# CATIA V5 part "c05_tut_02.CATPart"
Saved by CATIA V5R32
Part number: Part1
Bounding box of the stored display mesh (mm): x -5 to 20, y -42.072 to 42.072, z 0 to 101.82
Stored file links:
  D:\PROJECTS\Project 2022\CATIA V5 6R 2022\Resources\Tutorial Files\c05_catia_v5_6r2022_tut\c05_tut_02.CATPart
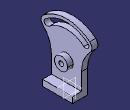
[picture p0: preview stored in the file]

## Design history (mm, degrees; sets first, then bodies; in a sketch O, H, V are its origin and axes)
Body1 (main body)
  Sketch1 on yz-plane, origin (0, 0, 0), H (0, 1, 0), V (0, 0, 1)
    point P1 (-25, 0)
    line L1 (-25, 0) -> (25, 0)
    point P2 (25, 0)
    line L2 (-25, 0) -> (-25, 38.3145)
    point P3 (-25, 38.3145)
    arc A1 centre (0, 42) radius 60 from (38.5673, 87.9627) to (-38.5673, 87.9627) ccw
    point P4 (0, 42)
    axis line L3 (0, 42) -> (-54.0665, 106.434)
    point P5 (-54.0665, 106.434)
    point P6 (54.0665, 106.434)
    point P7 (0, 42)
    construction line L4 (0, 42) -> (54.0665, 106.434)
    point P8 (-38.5673, 87.9627)
    point P9 (38.5673, 87.9627)
    arc A2 centre (-32.1394, 80.3022) radius 10 from (-38.5673, 87.9627) to (-39.2828, 73.3043) ccw
    point P10 (-32.1394, 80.3022)
    arc A3 centre (32.1394, 80.3022) radius 10 from (38.5673, 87.9627) to (39.2828, 73.3043) cw
    arc A4 centre (-75, 38.3145) radius 50 from (-25, 38.3145) to (-39.2828, 73.3043) ccw
    arc A5 centre (75, 38.3145) radius 50 from (25, 38.3145) to (39.2828, 73.3043) cw
    point P14 (25, 38.3145)
    point P15 (25, 0)
    line L5 (25, 0) -> (25, 38.3145)
    point P17 (25, 38.3145)
    length L1 = 50
    angle L4 L3 = 80
    radius A1 = 60
    radius A2 = 10
    radius A5 = 50
    distance P4 L1 = 42
    coincidence: P1 H, P4 V, L3 P8, L4 P9, P10 L3, L5 P17, P2 P15, P14 P17
    horizontal: L1 H
    symmetry: P2 P1 V, P5 P6 V, P4 P7 V, L3 L4 V, A2 A3 V, A4 A5 V, P3 P14 V, P1 P15 V, L2 L5 V
    vertical: L2 V
    tangency: A2 A1, A4 A2, A4 L2, A5 A3, L5 A5
  Pad1: profile Sketch1, direction (1, 0, 0), length 5, mirrored extent
  Sketch2 on start face of Pad1, origin (-5, 0, 0), H (0, -1, 0), V (0, 0, 1)
    construction arc A1 centre (0, 42) radius 50 from (32.1394, 80.3022) to (-32.1394, 80.3022) ccw
    point P1 (0, 42)
    arc A2 centre (32.1394, 80.3022) radius 5 from (35.3533, 84.1324) to (28.9254, 76.472) cw
    arc A3 centre (-32.1394, 80.3022) radius 5 from (-28.9254, 76.472) to (-35.3533, 84.1324) cw
    arc A4 centre (0, 42) radius 45 from (28.9254, 76.472) to (-28.9254, 76.472) ccw
    arc A5 centre (0, 42) radius 55 from (-35.3533, 84.1324) to (35.3533, 84.1324) cw
    construction line L1 (-32.1394, 80.3022) -> (0, 42)
    construction line L2 (0, 42) -> (32.1394, 80.3022)
    radius A3 = 5
    radius A1 = 50
    angle L2 L1 = 80
    angle L2 V = 40
    distance P1 H = 42
    coincidence: P1 V
    tangency: A4 A3, A3 A5, A5 A2, A2 A4
    concentricity: A4 P1, A5 P1
  Pocket1: profile Sketch2, direction (1, 0, 0), through (limit type 6)
  Sketch3 on end face of Pad1, origin (5, 0, 0), H (0, 1, 0), V (0, 0, 1)
    point P1 (-24.9592, 0)
    line L1 (-24.9592, 0) -> (25, 0)
    line L2 (25, 0) -> (25, 10)
    line L3 (25, 10) -> (-24.9592, 10)
    line L4 (-24.9592, 10) -> (-24.9592, 0)
    reference projected line E1 (25, 0) -> (25, 38.3145) from edge [face of Pad1 from Sketch1.L5 | end face of Pad1]
    distance L1 L3 = 10
    distance L2 L4 = 49.9592
    coincidence: P1 H, L2 E1
    horizontal: L1 H, L3 H
    vertical: L2 V, L4 V
  Pad2: profile Sketch3, direction (1, 0, 0), length 15
  Sketch4 on end face of Pad1, origin (5, 0, 0), H (0, 1, 0), V (0, 0, 1)
    circle A1 centre (0, 42) radius 11
    point P1 (0, 42)
    circle A2 centre (0, 42) radius 4
    axis line L1 (0, 0) -> (0, 71.4904)
    reference projected line E1 (-24.9592, 0) -> (25, 0) from edge [face of Pad2 | end face of Pad2]
    radius A1 = 11
    radius A2 = 4
    distance E1 P1 = 42
    coincidence: P1 V, P1 L1
    vertical: L1 V
  Pad3: profile Sketch4, direction (1, 0, 0), length 9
